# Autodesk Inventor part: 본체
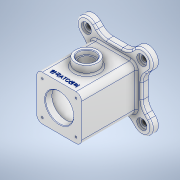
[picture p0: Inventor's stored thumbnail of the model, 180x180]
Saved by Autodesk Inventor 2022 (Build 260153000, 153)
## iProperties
Created: 2022-05
Part Number: 본체
Material: 알루미늄 6061
Document SubType Name: Modeling
Designer: Admin
Density: 2.7 g/cm^3
Appearance: 알루미늄 - 평지
Mass: 1073.05 g
Surface Area: 877.572 cm^2
Volume: 397.426 cm^3
Author: Admin
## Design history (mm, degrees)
sketch "스케치1"
  geometry: L1 (-56, 0)-(56, 0) reference; L2 (0, -56)-(0, 56) reference; L3 (-40, 40)-(40, 40); L4 (40, 40)-(40, -40); L5 (40, -40)-(-40, -40); L6 (-40, -40)-(-40, 40); L7 (-40, 40)-(40, -40); L8 (40, 40)-(-40, -40); 1 further point
  constraints: 12 end point, 2 midpoint, 2 parallel, 1 horizontal, 1 perpendicular
  dimensions: "d0" = 80 distance of L3.start L3.end; "d1" = 80 distance of L3.end L4.end
extrude "돌출1" new body sketch "스케치1" stored distance "d2" = 110; taper "d3" = 0 deg
fillet "모깎기1" dims "d4" = 10
sketch "스케치2"
  geometry: L1 (-22.753, 22.753)-(-9.988, 9.988); L2 (30, 40)-(-30, 40) reference; L3 (40, -30)-(40, 30) reference; L4 (30, 40)-(-30, 40) reference; L5 (-40, 30)-(-40, -30) reference; L6 (-30, -40)-(30, -40) reference; L7 (0, 0)-(-18.736, 18.736); L8 (0, -62.867)-(0, 82.702) reference; L9 (-49, 49)-(49, 49); L10 (49, 49)-(49, -49); L11 (49, -49)-(-49, -49); L12 (-49, -49)-(-49, 49); L13 (-49, 49)-(49, -49); L14 (49, 49)-(-49, -49); L15 (-49, 49)-(-40, 40); L16 (-61.728, 36.272)-(-52.728, 27.272); L17 (-27.272, 52.728)-(-36.272, 61.728); L18 (27.272, 52.728)-(36.272, 61.728); L19 (61.728, 36.272)-(52.728, 27.272); L20 (104.238, 0)-(-104.238, 0) reference; L21 (-61.728, -36.272)-(-52.728, -27.272); L22 (-27.272, -52.728)-(-36.272, -61.728); L23 (27.272, -52.728)-(36.272, -61.728); L24 (61.728, -36.272)-(52.728, -27.272); A1 r 10 centre (30, -30) between (30, -40) and (40, -30) reference; A2 r 10 centre (30, 30) between (40, 30) and (30, 40) reference; A3 r 10 centre (-30, 30) between (-30, 40) and (-40, 30) reference; A4 r 10 centre (-30, -30) between (-40, -30) and (-30, -40) reference; A5 r 18 centre (-49, 49) between (-36.272, 61.728) and (-61.728, 36.272); A6 r 18 centre (-40, 40) between (-52.728, 27.272) and (-27.272, 52.728); A7 r 18 centre (49, 49) between (61.728, 36.272) and (36.272, 61.728); A8 r 18 centre (40, 40) between (27.272, 52.728) and (52.728, 27.272); A9 r 18 centre (-49, -49) between (-61.728, -36.272) and (-36.272, -61.728); A10 r 18 centre (-40, -40) between (-27.272, -52.728) and (-52.728, -27.272); A11 r 18 centre (49, -49) between (36.272, -61.728) and (61.728, -36.272); A12 r 18 centre (40, -40) between (52.728, -27.272) and (27.272, -52.728); 9 further points
  constraints: 38 end point, 16 point on circle, 15 symmetric about line, 8 centre point, 4 tangent, 3 midpoint, 3 parallel, 3 point on line, 1 collinear, 1 horizontal, 1 perpendicular, 6 other
  dimensions: "d6" = 98 distance of L9.start L9.end; "d7" = 98 distance of L9.end L10.end; "d8" = 36 distance between parallel lines of L17 L16
extrude "돌출2" join sketch "스케치2" distance "d9" = 12; taper "d10" = 0 deg
sketch "스케치4" dims "d12" = 140
  geometry: L1 (-49.497, 49.497)-(0, 0); L2 (0, -104.342)-(0, 104.858) reference; L3 (-104.858, 0)-(104.342, 0) reference; L4 (49.497, 49.497)-(0, 0); L5 (-49.497, -49.497)-(0, 0); L6 (49.497, -49.497)-(0, 0); A1 r 18.014 centre (-49.497, 49.497) between (-36.272, 61.728) and (-61.728, 36.272); A2 r 18 centre (49, 49) between (61.728, 36.272) and (36.272, 61.728) reference; A3 r 18 centre (49, -49) between (36.272, -61.728) and (61.728, -36.272) reference; A4 r 18 centre (-49, -49) between (-61.728, -36.272) and (-36.272, -61.728) reference; 5 further points
  constraints: 8 end point, 5 coincident, 3 symmetric about line, 2 point on circle, 1 centre point, 3 other
hole "구멍1" sketch "스케치4" at (-49.497, 49.497), (49.497, 49.497), (49.497, -49.497), (-49.497, -49.497) diameter "d13" = 10; stored, may be unused: countersink angle "d17" = 90 deg, drill point angle "d19" = 118 deg; dims "d14" = 6, "d15" = 18, "d16" = 4, "d18" = 8
sketch "스케치5"
  geometry: L1 (-30, 30)-(30, 30); L2 (30, 30)-(30, -30); L3 (30, -30)-(-30, -30); L4 (-30, -30)-(-30, 30); L5 (-30, 30)-(30, -30); L6 (30, 30)-(-30, -30); A1 r 10 centre (-30, 30) between (-30, 40) and (-40, 30) reference; 5 further points
  constraints: 12 end point, 4 coincident, 2 midpoint, 2 parallel, 1 horizontal, 1 perpendicular
  dimensions: "d20" = 60 distance of L2.end L3.end; "d21" = 60 distance of L1.end L2.end
hole "구멍2" sketch "스케치5" at (-30, 30), (30, 30), (30, -30), (-30, -30) diameter "d22" = 3.242; stored, may be unused: countersink angle "d26" = 90 deg, drill point angle "d28" = 118 deg; dims "d23" = 8, "d24" = 18, "d25" = 4, "d27" = 10
node "작업 평면1"
sketch "스케치6"
  geometry: L1 (67, -43)-(36.272, -43) reference; C1 r 20 at (0, 6); 2 further points
  constraints: 1 centre point
  dimensions: "d31" = 40 diameter of C1; "d32" = 49 distance from line of L1 C1.centre
extrude "돌출3" join sketch "스케치6" stored distance "d33" = 12; taper "d34" = 0 deg
sketch "스케치7"
  geometry: C1 r 20 at (0, 0) reference; C2 r 15 at (0, 0)
  constraints: 1 centre point, 1 coincident
  dimensions: "d35" = 30 diameter of C2
extrude "돌출4" cut sketch "스케치7" distance "d36" = 8; taper "d37" = 0 deg
sketch "스케치9"
  geometry: L1 (0, -77)-(0, 77) reference; L2 (30, 55)-(-30, 55) reference; L3 (0, 55)-(25, 55); L4 (25, 55)-(25, 43); L5 (25, 43)-(0, 43); L6 (0, 43)-(0, 55); L7 (0, 43)-(35, 43); L8 (35, 43)-(35, -43); L9 (35, -43)-(0, -43); L10 (0, -43)-(0, 43); L11 (-24.412, -55)-(24.412, -55) reference; L12 (0, -43)-(25, -43); L13 (25, -43)-(25, -55); L14 (25, -55)-(0, -55); L15 (0, -55)-(0, -43); 6 further points
  constraints: 24 end point, 6 parallel, 3 horizontal, 3 perpendicular, 1 midpoint, 1 point on line
  dimensions: "d38" = 12 distance between parallel lines of L5 L2; "d39" = 86 distance between parallel lines of L12 L7; "d40" = 50 diameter of L4 L1; "d41" = 50 diameter of L13 L1; "d42" = 70 diameter of L8 L1
revolve "회전1" sketch "스케치9" stored, may be unused: angle "d43" = 90 deg
sketch "스케치10"
  geometry: C1 r 15 at (0, 0) reference; C2 r 12.5 at (0, 0); 1 further point
  constraints: 1 centre point, 1 coincident
  dimensions: "d44" = 25 diameter of C2
extrude "돌출5" cut sketch "스케치10" stored distance "d45" = 8; taper "d46" = 0 deg
sketch "스케치11"
  geometry: L1 (-30, 30)-(30, 30); L2 (30, 30)-(30, -30); L3 (30, -30)-(-30, -30); L4 (-30, -30)-(-30, 30); L5 (-30, 30)-(30, -30); L6 (30, 30)-(-30, -30); C1 r 1.621 at (-30, 30) reference; C2 r 1.621 at (30, -30) reference; 5 further points
  constraints: 12 end point, 4 coincident, 2 midpoint, 2 parallel, 1 horizontal, 1 perpendicular
  dimensions: "d47" = 60 distance of L2.end L3.end; "d48" = 60 distance of L1.end L2.end
hole "구멍3" sketch "스케치11" at (-30, 30), (30, 30), (30, -30), (-30, -30) diameter "d49" = 3.242; stored, may be unused: countersink angle "d53" = 90 deg, drill point angle "d55" = 118 deg; dims "d50" = 8, "d51" = 4, "d52" = 2, "d54" = 10
fillet "모깎기2" dims "d56" = 25
fillet "모깎기3" dims "d57" = 3
fillet "모깎기4" dims "d58" = 3
chamfer "모따기1" distance "d59" = 1; stored, may be unused: second distance "d60" = 2, angle "d61" = 45 deg
fillet "모깎기5" dims "d62" = 3
sketch "스케치12"
  geometry: L1 (60, 0)-(0, 0) reference; L2 (30, 132)-(30, -22) reference; 2 further points
  constraints: 1 point on line, 1 other
  dimensions: "d63" = 10 distance from line of L1 point (30, 10)
feature "엠보싱1" sketch "스케치12" dims "d0" = 80, "d1" = 80, "d64" = 0.5, "d65" = 0
node "솔리드1"
node "투영된 루프1"
node "투영된 루프2"
feature "A9D066F2-1C7D-4E18-AEED-F7BC21143FA4" dims "d13" = 10, "d14" = 6, "d15" = 18, "d16" = 4, "d17" = 90 deg, "d18" = 8, "d19" = 118 deg
other parameters: "d29" = 55
